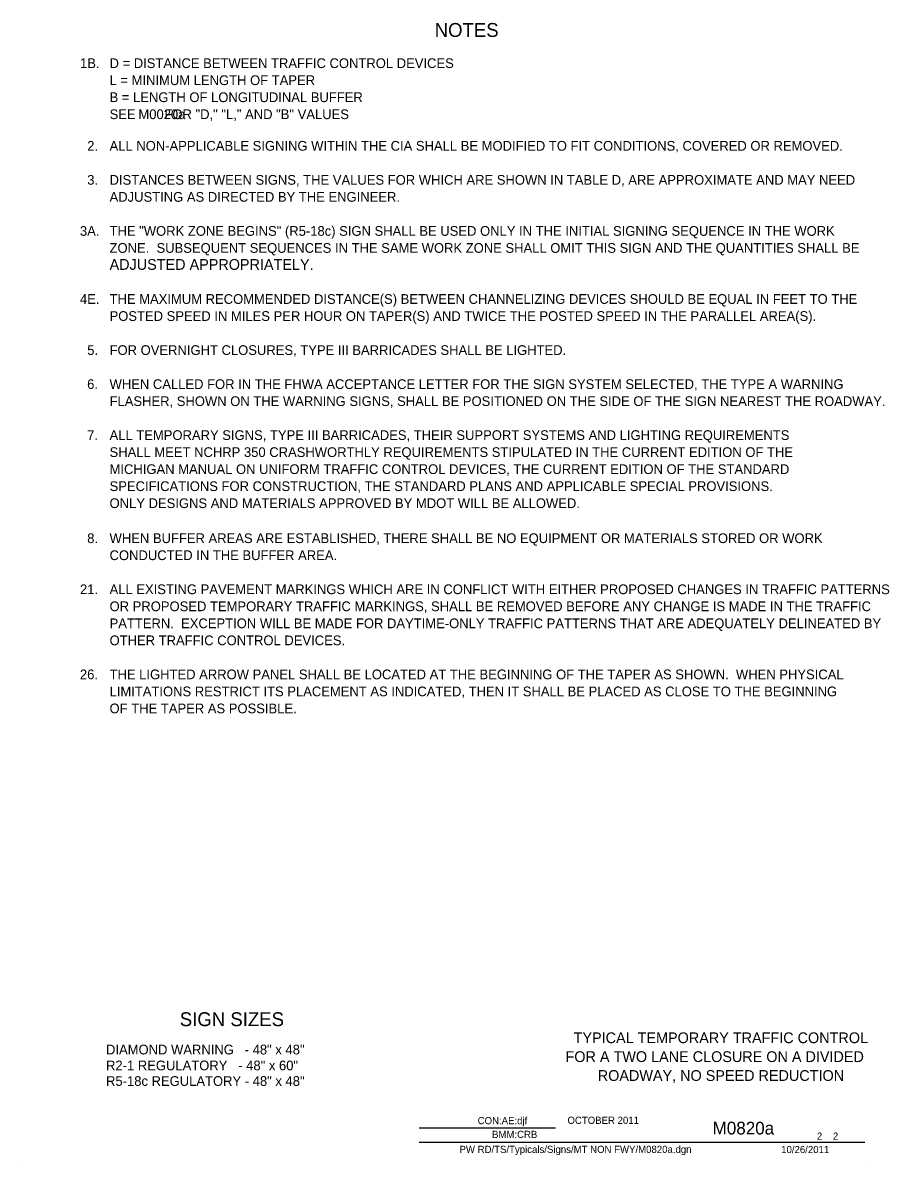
# Model space of a CAD drawing. Extents: x 16745 to 18475, y 7012 to 8195.
# Drawn here: x 17727 to 18475, y 7211 to 8195 of the extents above; entities that cross this region are included whole.
import ezdxf

# ---------------------------------------------------------------- set-up
doc = ezdxf.new("R2010")
doc.units = 0
for name, color, linetype in [('BORDER', 7, 'Continuous'), ('BORDER_SIGNAL_WO', 7, 'Continuous'), ('TYPICAL_TEXT_DIMEN_PR', 7, 'Continuous')]:
    doc.layers.add(name, color=color, linetype=linetype)

msp = doc.modelspace()

# ---------------------------------------------------------------- linework, layer by layer
at = {"layer": 'BORDER'}
for p, q in [((18069.04, 7241.25), (18187.04, 7241.25)), ((18069.04, 7228.75), (18454.04, 7228.75)), ((17726.74, 7210.65), (17726.74, 7210.65)), ((18454.84, 7210.65), (18454.84, 7210.65))]:
    msp.add_line(p, q, dxfattribs=at)

# ---------------------------------------------------------------- texts
for s, p in [('TYPICAL TEMPORARY TRAFFIC CONTROL', (18202.63, 7314.3)), ('FOR A TWO LANE CLOSURE ON A DIVIDED', (18195.61, 7298)), ('ROADWAY, NO SPEED REDUCTION', (18223.44, 7281.7))]:
    msp.add_text(s, height=9.3, dxfattribs=at).set_placement(p)
at = {"layer": 'BORDER_SIGNAL_WO'}
for s, height, p in [('CON:AE:djf', 6.2, (18119.69, 7244.31)), ('    OCTOBER 2011    ', 6.2, (18188.08, 7244.59)), ('BMM:CRB   ', 6.2, (18132.1, 7232.42)), ('    M0820a   ', 11, (18306.32, 7235.43)), (' 2    2 ', 6.2, (18410.45, 7230.95)), ('PW RD/TS/Typicals/Signs/MT NON FWY/M0820a.dgn    ', 6.2, (18104.01, 7219.49)), ('10/26/2011    ', 6.2, (18381.93, 7219.38))]:
    msp.add_text(s, height=height, dxfattribs=at).set_placement(p)
at = {"layer": 'TYPICAL_TEXT_DIMEN_PR'}
for s, height, p in [('NOTES', 12, (18082.55, 8183.25)), ('1B.', 8.4, (17776.19, 8156.36)), ('D = DISTANCE BETWEEN TRAFFIC CONTROL DEVICES', 8.4, (17801.7, 8156.36)), ('L = MINIMUM LENGTH OF TAPER', 8.4, (17801.7, 8141.66)), ('B = LENGTH OF LONGITUDINAL BUFFER', 8.4, (17801.7, 8126.96)), ('SEE        FOR "D," "L," AND "B" VALUES', 8.4, (17801.7, 8112.26)), ('M0020a', 8.4, (17826.62, 8112.26)), ('2.', 8.4, (17782.39, 8085)), ('ALL NON-APPLICABLE SIGNING WITHIN THE CIA SHALL BE MODIFIED TO FIT CONDITIONS, COVERED OR REMOVED.', 8.4, (17801.7, 8085)), ('3.', 8.4, (17782.39, 8055.6)), ('DISTANCES BETWEEN SIGNS, THE VALUES FOR WHICH ARE SHOWN IN TABLE D, ARE APPROXIMATE AND MAY NEED', 8.4, (17801.7, 8055.6)), ('ADJUSTING AS DIRECTED BY THE ENGINEER.', 8.4, (17801.7, 8040.9)), ('3A.', 8.4, (17776.09, 8011.5)), ('THE "WORK ZONE BEGINS" (R5-18c) SIGN SHALL BE USED ONLY IN THE INITIAL SIGNING SEQUENCE IN THE WORK', 8.4, (17801.7, 8011.5)), ('ZONE.  SUBSEQUENT SEQUENCES IN THE SAME WORK ZONE SHALL OMIT THIS SIGN AND THE QUANTITIES SHALL BE', 8.4, (17801.7, 7996.8)), ('ADJUSTED APPROPRIATELY.', 9.3, (17801.7, 7982.1)), ('4E.', 8.4, (17776.13, 7952.7)), ('THE MAXIMUM RECOMMENDED DISTANCE(S) BETWEEN CHANNELIZING DEVICES SHOULD BE EQUAL IN FEET TO THE', 8.4, (17801.7, 7952.7)), ('POSTED SPEED IN MILES PER HOUR ON TAPER(S) AND TWICE THE POSTED SPEED IN THE PARALLEL AREA(S).', 8.4, (17801.7, 7938)), ('5.', 8.4, (17782.39, 7908.6)), ('FOR OVERNIGHT CLOSURES, TYPE III BARRICADES SHALL BE LIGHTED.', 8.4, (17801.7, 7908.6)), ('6.', 8.4, (17782.34, 7879.2)), ('WHEN CALLED FOR IN THE FHWA ACCEPTANCE LETTER FOR THE SIGN SYSTEM SELECTED, THE TYPE A WARNING ', 8.4, (17801.7, 7879.2)), ('FLASHER, SHOWN ON THE WARNING SIGNS, SHALL BE POSITIONED ON THE SIDE OF THE SIGN NEAREST THE ROADWAY.', 8.4, (17801.7, 7864.5)), ('7.', 8.4, (17782.34, 7835.16)), ('ALL TEMPORARY SIGNS, TYPE III BARRICADES, THEIR SUPPORT SYSTEMS AND LIGHTING REQUIREMENTS', 8.4, (17801.7, 7835.18)), ('SHALL MEET NCHRP 350 CRASHWORTHLY REQUIREMENTS STIPULATED IN THE CURRENT EDITION OF THE', 8.4, (17801.7, 7820.48)), ('MICHIGAN MANUAL ON UNIFORM TRAFFIC CONTROL DEVICES, THE CURRENT EDITION OF THE STANDARD', 8.4, (17801.7, 7805.78)), ('SPECIFICATIONS FOR CONSTRUCTION, THE STANDARD PLANS AND APPLICABLE SPECIAL PROVISIONS.', 8.4, (17801.7, 7791.08)), ('ONLY DESIGNS AND MATERIALS APPROVED BY MDOT WILL BE ALLOWED.', 8.4, (17801.7, 7776.38)), ('8.', 8.4, (17782.39, 7746.15)), ('WHEN BUFFER AREAS ARE ESTABLISHED, THERE SHALL BE NO EQUIPMENT OR MATERIALS STORED OR WORK     ', 8.4, (17801.7, 7746.15)), ('CONDUCTED IN THE BUFFER AREA.', 8.4, (17801.7, 7731.45)), ('21.', 8.4, (17776.14, 7702.05)), ('ALL EXISTING PAVEMENT MARKINGS WHICH ARE IN CONFLICT WITH EITHER PROPOSED CHANGES IN TRAFFIC PATTERNS', 8.4, (17801.7, 7702.05)), ('OR PROPOSED TEMPORARY TRAFFIC MARKINGS, SHALL BE REMOVED BEFORE ANY CHANGE IS MADE IN THE TRAFFIC', 8.4, (17801.7, 7687.35)), ('PATTERN.  EXCEPTION WILL BE MADE FOR DAYTIME-ONLY TRAFFIC PATTERNS THAT ARE ADEQUATELY DELINEATED BY', 8.4, (17801.7, 7672.65)), ('OTHER TRAFFIC CONTROL DEVICES.', 8.4, (17801.7, 7657.95)), ('26.', 8.4, (17776.09, 7628.55)), ('THE LIGHTED ARROW PANEL SHALL BE LOCATED AT THE BEGINNING OF THE TAPER AS SHOWN.  WHEN PHYSICAL', 8.4, (17801.7, 7628.55)), ('LIMITATIONS RESTRICT ITS PLACEMENT AS INDICATED, THEN IT SHALL BE PLACED AS CLOSE TO THE BEGINNING', 8.4, (17801.7, 7613.85)), ('OF THE TAPER AS POSSIBLE.', 8.4, (17801.7, 7599.15)), ('SIGN SIZES', 12, (17862.35, 7328.98)), ('DIAMOND WARNING   - 48" x 48"', 8.4, (17798.65, 7304.58)), ('R2-1 REGULATORY   - 48" x 60"', 8.4, (17798.65, 7290.84)), ('R5-18c REGULATORY - 48" x 48"', 8.4, (17798.65, 7277.4))]:
    msp.add_text(s, height=height, dxfattribs=at).set_placement(p)

doc.saveas('drawing.dxf')
